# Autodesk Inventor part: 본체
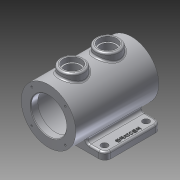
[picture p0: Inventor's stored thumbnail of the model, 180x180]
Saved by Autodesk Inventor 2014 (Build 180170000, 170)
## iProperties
Created: 2014-12
Part Number: 본체
Material: 알루미늄 6061
Document SubType Name: Modeling
Designer: Owner
Density: 2.71 g/cm^3
Appearance: 알루미늄 - 평지
Mass: 1293.23 g
Surface Area: 1041.82 cm^2
Volume: 477.206 cm^3
Author: Owner
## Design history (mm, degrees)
sketch "스케치1"
  geometry: C1 r 46 at (0, 0); 1 further point
  constraints: 1 centre point, 1 coincident
  dimensions: "d0" = 92 diameter of C1
extrude "돌출1" new body sketch "스케치1" distance "d1" = 140; taper "d2" = 0 deg
node "작업 평면1"
sketch "스케치2"
  geometry: L1 (65, -38)-(65, -50); L2 (65, -50)-(-65, -50); L3 (-65, -50)-(-65, -38); L4 (-65, -38)-(-38.884, -38); L5 (38.884, -38)-(65, -38); A1 r 46 centre (0, 0) between (-35.072, -29.765) and (35.072, -29.765) reference; A2 r 5 centre (-38.884, -33) between (-38.884, -38) and (-35.072, -29.765); A3 r 5 centre (38.884, -33) between (35.072, -29.765) and (38.884, -38); 2 further points
  constraints: 10 end point, 6 point on circle, 6 tangent, 3 parallel, 2 centre point, 2 horizontal, 2 perpendicular, 1 equal radius, 1 midpoint, 1 vertical alignment
  dimensions: "d4" = 50 distance from line of L2 point (0, 0); "d5" = 12 distance of L2.end L3.end; "d6" = 5 radius of A3; "d7" = 130 distance between parallel lines of L1 L3
extrude "돌출2" join sketch "스케치2" distance "d8" = 95; taper "d9" = 0 deg
node "작업 평면2"
sketch "스케치3"
  geometry: L1 (-46, 0)-(46, 0) reference; C1 r 20 at (0, 100); C2 r 20 at (0, 40); 1 further point
  constraints: 2 centre point, 2 vertical alignment, 1 equal radius
  dimensions: "d11" = 40 diameter of C1; "d12" = 40 distance from line of C2.centre L1; "d13" = 60 distance of C2.centre C1.centre
extrude "돌출3" join sketch "스케치3" stored distance "d14" = 95; taper "d15" = 0 deg
sketch "스케치4"
  geometry: L1 (26.116, 0)-(0, 0) reference; L2 (0, 95)-(26.116, 95) reference; 3 further points
  constraints: 1 vertical alignment
  dimensions: "d17" = 12.5 distance from line of L2 point (13.116, 82.5); "d18" = 12.5 distance from line of L1 point (13.116, 12.5); "d19" = 52 horizontal distance of point (13.116, 12.5) point (-38.884, -30)
hole "구멍1" sketch "스케치4" at (13.116, 82.5), (13.116, 12.5) diameter "d20" = 11; stored, may be unused: countersink angle "d24" = 90 deg, drill point angle "d26" = 0 deg; dims "d21" = 6, "d22" = 4, "d23" = 2, "d25" = 8
fillet "모깎기1" dims "d27" = 10
hole "구멍2" diameter "d30" = 30; stored, may be unused: countersink angle "d34" = 90 deg, drill point angle "d36" = 0 deg; dims "d28" = 10, "d29" = 10, "d31" = 6, "d32" = 4, "d33" = 2, "d35" = 8
hole "구멍3" diameter "d39" = 30; stored, may be unused: countersink angle "d43" = 90 deg, drill point angle "d45" = 0 deg; dims "d37" = 10, "d38" = 10, "d40" = 6, "d41" = 4, "d42" = 2, "d44" = 8
hole "구멍4" diameter "d48" = 60; stored, may be unused: countersink angle "d52" = 90 deg, drill point angle "d54" = 0 deg; dims "d46" = 10, "d47" = 10, "d49" = 6, "d50" = 4, "d51" = 2, "d53" = 12
hole "구멍5" diameter "d57" = 60; stored, may be unused: countersink angle "d61" = 90 deg, drill point angle "d63" = 0 deg; dims "d55" = 10, "d56" = 10, "d58" = 6, "d59" = 4, "d60" = 2, "d62" = 12
hole "구멍6" diameter "d66" = 75; stored, may be unused: countersink angle "d70" = 90 deg, drill point angle "d72" = 0 deg; dims "d64" = 10, "d65" = 10, "d67" = 6, "d68" = 4, "d69" = 2, "d71" = 116
hole "구멍7" diameter "d75" = 25; stored, may be unused: countersink angle "d79" = 90 deg, drill point angle "d81" = 0 deg; dims "d73" = 10, "d74" = 10, "d76" = 6, "d77" = 4, "d78" = 2, "d80" = 116
hole "구멍8" diameter "d84" = 25; stored, may be unused: countersink angle "d88" = 90 deg, drill point angle "d90" = 0 deg; dims "d82" = 10, "d83" = 10, "d85" = 6, "d86" = 4, "d87" = 2, "d89" = 116
sketch "스케치5"
  geometry: L1 (26.116, 10)-(26.116, 85) reference; C1 r 5.5 at (13.116, 12.5) reference; 2 further points
  constraints: 1 other
  dimensions: "d91" = 35 vertical distance of C1.centre point (18.116, 47.5); "d92" = 8 distance from line of L1 point (18.116, 47.5)
feature "엠보싱1" sketch "스케치5" dims "d1" = 140, "d93" = 1, "d94" = 0
sketch "스케치6"
  geometry: L1 (0, 0)-(28.284, 28.284); L2 (0, 0)-(40, 0); C1 r 46 at (0, 0) reference; 1 further point
  constraints: 4 end point, 1 coincident, 1 equal length, 1 horizontal
  dimensions: "d95" = 40 distance of L1.start L1.end; "d96" = 45 deg angle of L2 L1
hole "구멍9" sketch "스케치6" at (28.284, 28.284) diameter "d97" = 3.242; stored, may be unused: countersink angle "d101" = 90 deg, drill point angle "d103" = 118 deg; dims "d98" = 8, "d99" = 4, "d100" = 2, "d102" = 10
sketch "스케치7"
  geometry: L1 (0, 0)-(28.284, 28.284); L2 (0, 0)-(40, 0); C1 r 46 at (0, 0) reference; 1 further point
  constraints: 4 end point, 1 coincident, 1 equal length, 1 horizontal
  dimensions: "d107" = 40 distance of L1.start L1.end; "d108" = 45 deg angle of L2 L1
hole "구멍10" sketch "스케치7" at (28.284, 28.284) diameter "d109" = 3.242; stored, may be unused: countersink angle "d113" = 90 deg, drill point angle "d115" = 118 deg; dims "d110" = 8, "d111" = 4, "d112" = 2, "d114" = 10
fillet "모깎기2" dims "d119" = 3
fillet "모깎기3" dims "d120" = 3
chamfer "모따기1" distance "d121" = 1; stored, may be unused: second distance "d122" = 2, angle "d123" = 45 deg
chamfer "모따기2" distance "d124" = 1; stored, may be unused: second distance "d125" = 2, angle "d126" = 45 deg
fillet "모깎기4" dims "d127" = 3
fillet "모깎기5" dims "d128" = 3
node "솔리드1"
mirror "대칭1"
pattern_circular "원형 패턴1" dims angle "d105" = 360 deg
pattern_circular "원형 패턴2" dims angle "d117" = 360 deg
other parameters: "d10" = 56
